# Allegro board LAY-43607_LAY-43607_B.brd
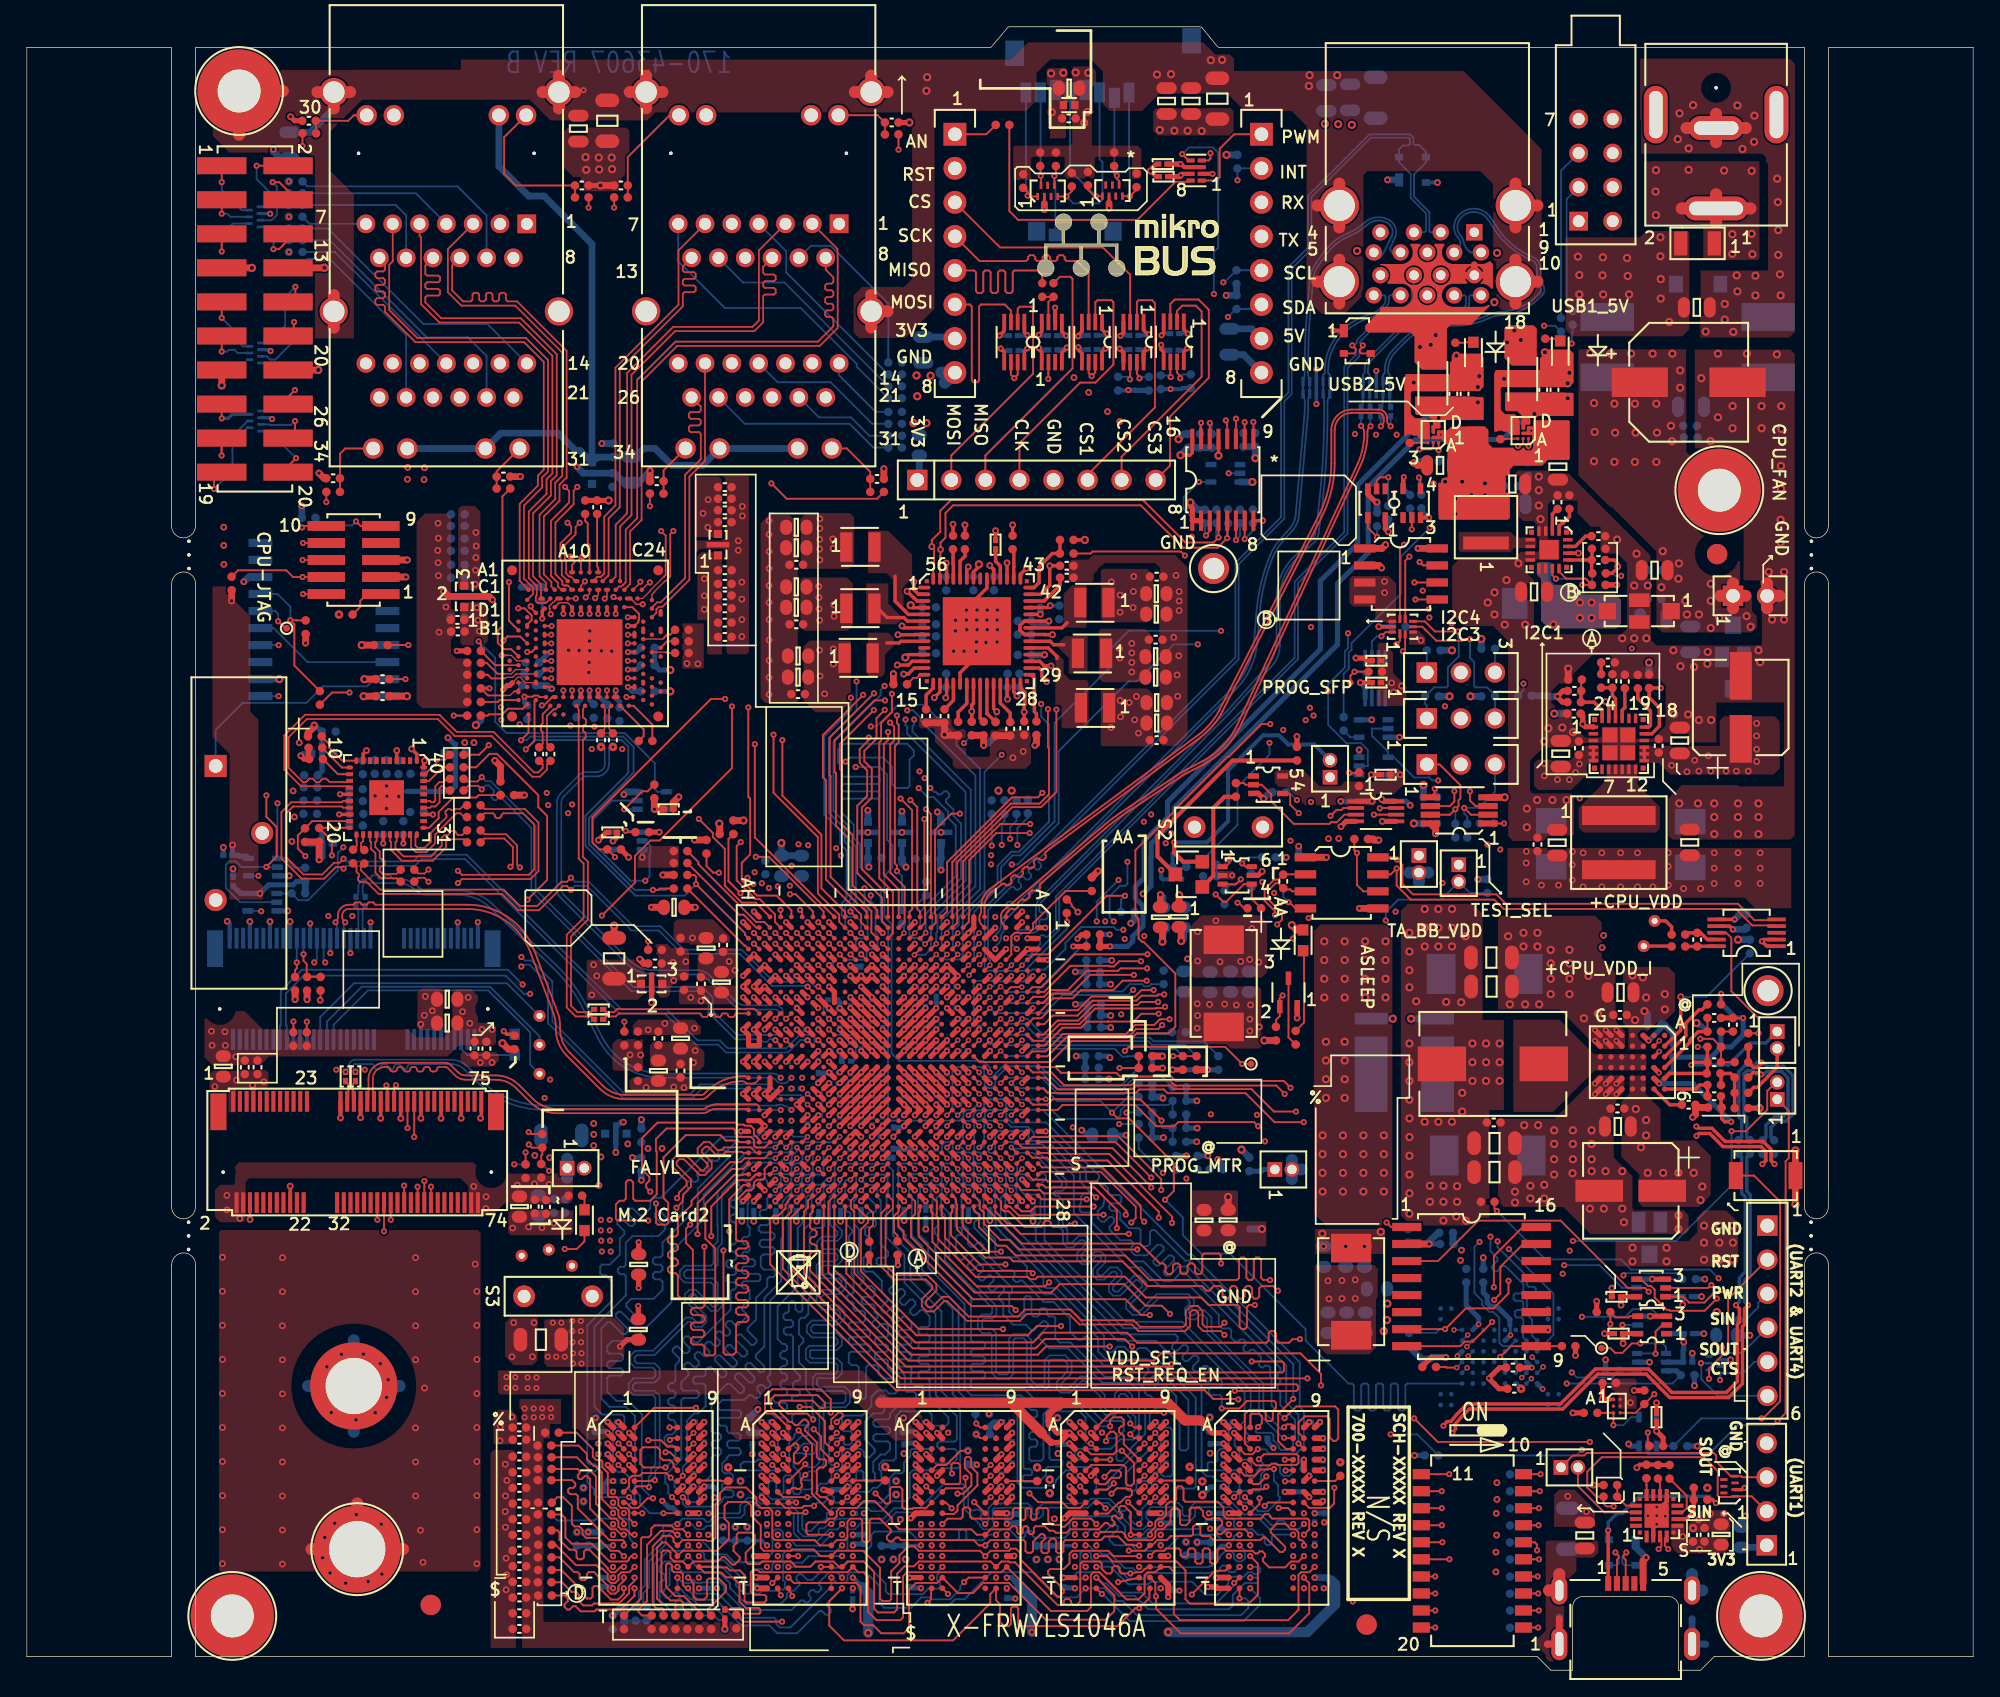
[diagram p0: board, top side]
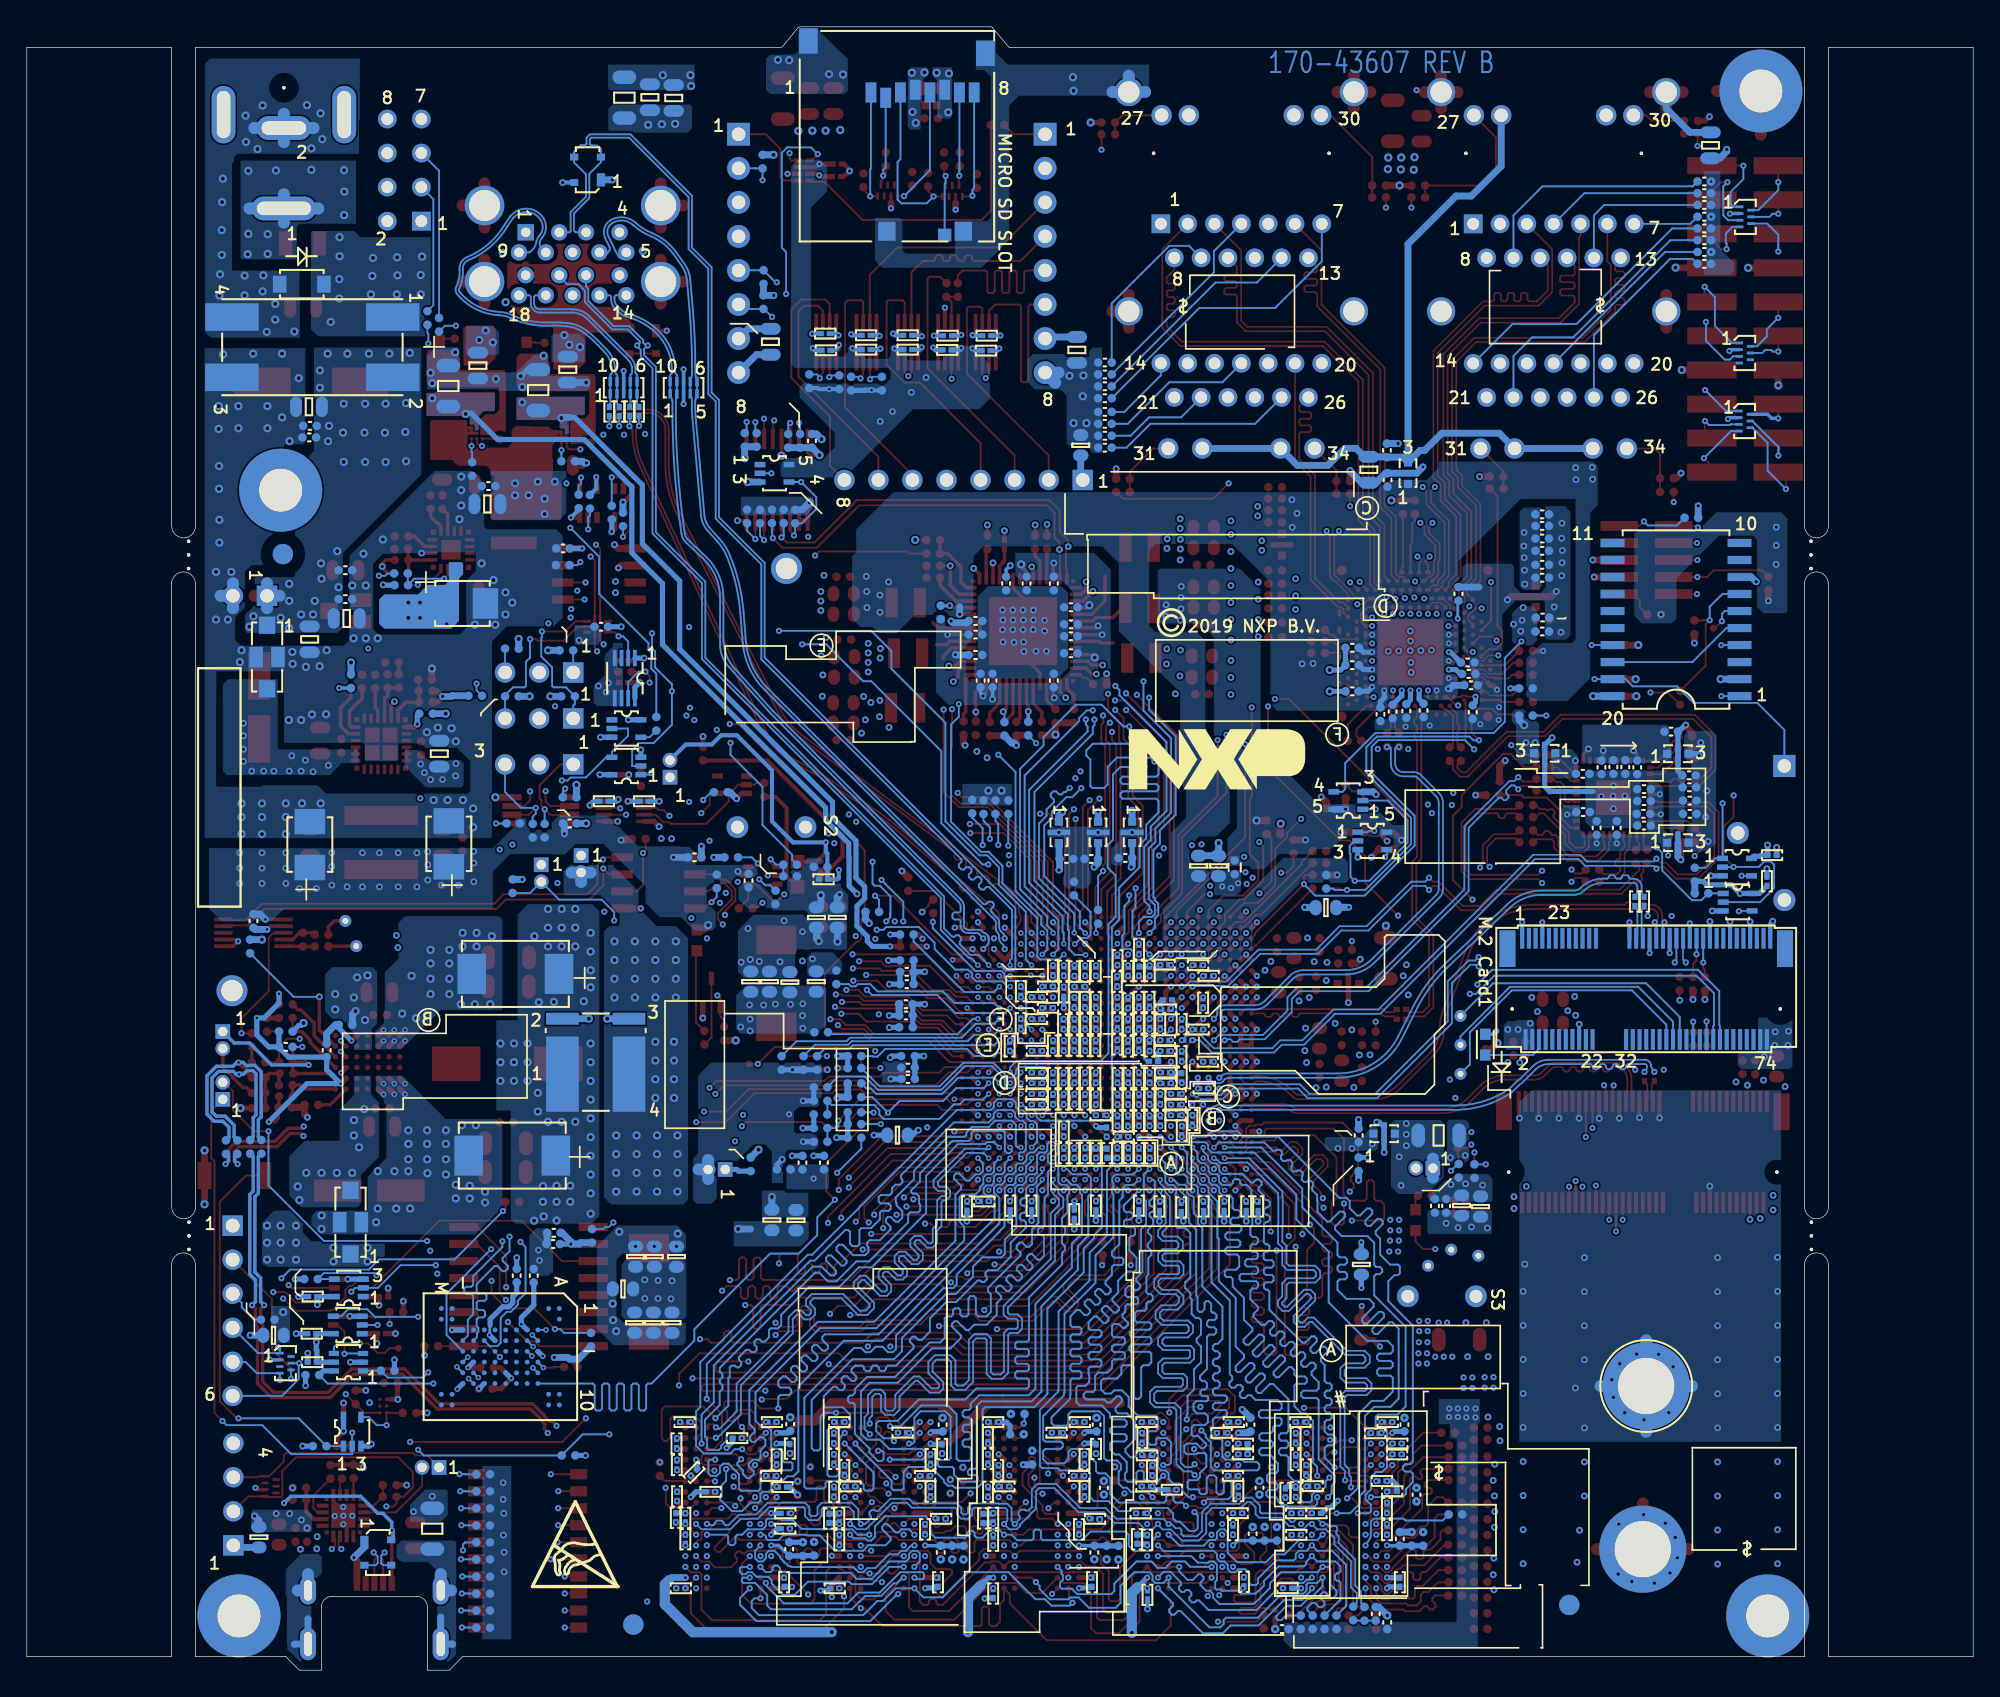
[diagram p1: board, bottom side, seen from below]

Outline 145.16 x 122.6 mm; copper layers: TOP, L2_GND, L3_INT_1, L4_INT_2, L5_PWR, BOTTOM. Coordinates in mm from the lower left corner of the outline.
Outline path: 0,121.05 10.8,121.05 10.8,85.36 arc(11.68,84.47) 12.57,85.36 12.57,121.05 71.8,121.05 arc(71.88,121.06) 71.94,121.1 73.14,122.54 arc(73.2,122.58) 73.26,122.6 87.45,122.6 arc(87.56,122.58) 87.66,122.51 88.77,121.15 arc(88.87,121.08) 88.99,121.05 132.57,121.05 132.57,85.36 arc(133.46,84.47) 134.35,85.36 134.36,85.36 134.36,121.05 145.16,121.05 145.16,1.02 134.36,1.02 134.36,30.24 arc(133.47,31.13) 132.58,30.24 132.57,1.02 125.84,1.02 124.83,0 123.19,0 123.19,4.7 arc(122.96,5.27) 122.39,5.5 116.09,5.5 arc(115.52,5.27) 115.29,4.7 115.29,0 113.65,0 112.64,1.01 112.63,1.02 12.57,1.02 12.58,30.24 arc(11.69,31.13) 10.81,30.24 10.8,30.24 10.8,1.02 0,1.02 0,121.05 ; 10.81,81.04 10.8,34.56 arc(11.68,33.67) 12.57,34.56 12.58,81.04 arc(11.69,81.93) 10.81,81.04 ; 132.58,81.04 132.57,34.56 arc(133.46,33.67) 134.35,34.56 134.36,81.04 arc(133.47,81.93) 132.58,81.04

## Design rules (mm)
constraint set DEFAULT: min track width 0.137
net group D1_MDQS8: nets D1_MDQS8_N D1_MDQS8_P
net group DP1: nets N26564871 N26564875
net group ETH_QSG3_MDI1: nets QSG3_MDI1_N QSG3_MDI1_P
net group QSGMII_RX_C: nets N29074387 N29074390
net group PH: nets IFC_CLE IFC_WE_B IFC_WP_B
net group POWER: nets 2V5_LED
net group SD_CLK: nets SOC_SD_CLK
net group U50: nets I2C_ADDR_A0 M2_1_REFCLK_EN# M2_2_REFCLK_EN#

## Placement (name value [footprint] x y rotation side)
BH5  -  [PMC_MECH_HOLE]  15.83 117.81 0 top
BH6  -  [PMC_MECH_HOLE]  15.32 4.05 0 top
BH7  -  [PMC_MECH_HOLE]  129.33 4.05 0 top
BH8  -  [PMC_MECH_HOLE]  126.22 88.03 0 top
BH9  -  [MH_C256-165T]  24.64 9.03 0 top
BH10  -  [MH_C256-165T]  24.38 21.2 180 bottom
BT3  -  [SKT_BAT_225X886_3V]  14.08 67.45 270 top
C5  -  [8X10P8]  123.94 96.08 0 top
C12  -  [CC0402_25]  121.4 79.9 180 bottom
C14  -  [CC0805_OV]  121.4 82.06 180 top
C18  -  [CC0402_25]  117.21 84.6 180 top
C19  -  [CC0402_25]  117.21 82.82 0 top
C20  -  [CC0805_OV]  110.79 88.49 0 top
C21  -  [CC0805_OV]  110.81 87 0 bottom
C22  -  [CC0402_25]  110.72 88.33 0 bottom
C24  -  [CC0805_OV]  118.86 50.56 180 top
C25  -  [CC0402_25]  118.81 48.88 180 top
C26  -  [CC0402_25]  118.63 41.9 180 top
C27  -  [CCE6P8X6P8]  119.62 35.77 180 top
C28  -  [CC0805_OV]  118.66 40.56 180 top
C29  22uF  [CC0805_OV]  124.55 101.67 0 top
C30  -  [CC0402_25]  124.04 92.83 0 bottom
C31  -  [CC0805_OV]  124.11 94.25 0 bottom
C32  -  [CC0402_25]  124.09 91.97 0 bottom
C36  -  [CC0402_25]  122.79 46.25 270 bottom
C113  -  [CC0402_25]  109.4 40.86 0 top
C114  100UF  [CC1206_OV]  109.22 53.16 0 top
C115  100UF  [CC1206_OV]  109.24 51 0 top
C116  100UF  [CC1206_OV]  109.46 37.16 0 top
C118  100UF  [CC1206_OV]  109.46 39.32 0 top
C119  -  [CC7343-31]  108.72 51.94 0 bottom
C120  -  [CC7343-31]  108.95 38.39 0 bottom
C122  100pF  [CC0402_25]  125.84 45.36 180 top
C125  -  [CC0402_25]  123.94 42.18 0 top
C126  -  [CC0402_25]  125.84 42.82 0 top
C127  56PF  [CC0402_25]  125.84 48.66 0 top
C128  -  [CC0402_25]  127.24 48.15 90 top
C148  -  [CC0201]  67.82 52.18 90 bottom
C149  -  [CC0201]  68.64 52.2 90 bottom
C151  -  [CC0402_25]  67.63 60.52 180 bottom
C152  -  [CC0201]  66.66 50.98 180 bottom
C153  -  [CC0201]  67.04 52.13 90 bottom
C155  -  [CC0402_25]  65.77 60.52 0 bottom
C156  -  [CC0201]  68.98 51.01 0 bottom
C157  -  [CC0201]  67.82 50.58 270 bottom
C159  -  [CC0402_25]  63.23 60.6 0 bottom
C160  -  [CC0201]  60.31 52.63 180 bottom
C161  -  [CC0603_OV]  57.77 60 90 bottom
C162  -  [CC0201]  65.08 41.39 180 bottom
C163  -  [CC0201]  71.04 48.27 90 bottom
C164  -  [CC0201]  63.03 49.74 90 bottom
C165  -  [CC0201]  63.82 49.85 270 bottom
C166  -  [CC0603_OV]  89.59 33.58 270 top
C167  -  [CC0603_OV]  89.59 33.58 270 bottom
C168  -  [CC0603_OV]  87.79 33.57 270 top
C169  -  [CC0603_OV]  84.54 56.18 90 top
C170  -  [CC0603_OV]  87.79 33.57 270 bottom
C171  -  [CC0603_OV]  86.27 56.15 90 bottom
C172  -  [CC0603_OV]  85.94 56.2 90 top
C173  -  [CC0603_OV]  84.72 56.15 90 bottom
C174  -  [CC0603_OV]  89.77 51.36 270 bottom
C175  -  [CC0603_OV]  91.17 51.36 270 bottom
C176  -  [CC0603_OV]  88.25 51.33 270 bottom
C180  -  [CC7343-31]  89.26 51.24 270 top
C181  -  [CC0201]  62.22 49.85 270 bottom
C182  -  [CC0201]  61.42 49.85 90 bottom
C183  -  [CC0201]  63.82 48.25 270 bottom
C184  -  [CC0201]  63.03 48.14 90 bottom
C185  -  [CC0201]  62.22 48.25 270 bottom
C186  -  [CC0201]  61.42 48.25 90 bottom
C187  -  [CC0201]  60.62 48.25 270 bottom
C188  -  [CC0201]  63.84 46.68 270 bottom
C189  -  [CC0201]  60.61 40.98 270 bottom
C190  -  [CC0201]  61.42 40.98 90 bottom
C191  -  [CC0201]  62.21 40.98 270 bottom
C193  -  [CC0201]  63.03 46.54 90 bottom
C194  -  [CC0201]  62.22 46.65 270 bottom
C195  -  [CC0201]  61.42 46.54 90 bottom
C196  -  [CC0201]  65.44 49.84 90 bottom
C197  -  [CC0201]  66.25 49.81 270 bottom
C198  -  [CC0201]  67.04 49.81 90 bottom
C199  -  [CC0201]  65.44 48.21 90 bottom
C200  -  [CC0201]  66.22 48.21 270 bottom
C201  -  [CC0201]  67.04 48.19 90 bottom
C202  -  [CC0201]  67.88 48.19 270 bottom
C203  -  [CC0201]  63.05 40.97 90 bottom
C204  -  [CC0201]  63.81 40.98 270 bottom
C205  -  [CC0201]  65.44 42.55 90 bottom
C206  -  [CC0201]  65.46 46.56 90 bottom
C207  -  [CC0201]  66.22 46.56 270 bottom
C208  -  [CC0201]  67.04 46.59 90 bottom
C209  -  [CC0201]  67.82 46.59 270 bottom
C210  -  [CC0201]  68.64 46.59 90 bottom
C211  -  [CC0201]  61.4 44.18 90 bottom
C212  -  [CC0201]  62.21 44.2 270 bottom
C213  -  [CC0201]  63 44.18 90 bottom
C214  -  [CC0201]  67.04 42.6 90 bottom
C215  -  [CC0201]  66.25 42.58 270 bottom
C216  -  [CC0201]  67.85 42.58 270 bottom
C217  -  [CC0201]  68.63 42.58 90 bottom
C218  -  [CC0201]  67.82 40.18 270 bottom
C219  -  [CC0201]  63.81 44.18 270 bottom
C220  -  [CC0201]  65.46 44.18 90 bottom
C221  -  [CC0201]  66.25 44.2 270 bottom
C222  -  [CC0201]  67.04 44.18 90 bottom
C223  -  [CC0201]  67.85 44.18 270 bottom
C224  -  [CC0201]  68.64 44.18 90 bottom
C225  -  [CC0201]  60.61 42.58 270 bottom
C226  -  [CC0201]  61.42 42.58 90 bottom
C227  -  [CC0201]  62.21 42.55 270 bottom
C228  -  [CC0201]  63.02 42.55 90 bottom
C229  -  [CC0201]  63.81 42.55 270 bottom
C230  -  [CC0402_25]  79.59 48.84 0 bottom
C231  -  [CC0402_25]  79.59 49.68 0 bottom
C232  -  [CC0201]  59.04 48.19 270 bottom
C233  -  [CC0402_25]  50.28 51.2 90 top
C234  -  [CC0603_OV]  51.8 51.33 90 top
C235  -  [CC0402_25]  79.44 44.1 0 bottom
C236  -  [CC0402_25]  79.44 44.95 0 bottom
C237  -  [CC0201]  57.8 52.6 180 bottom
C238  -  [CC0402_25]  51.93 54.09 270 top
C239  -  [CC0603_OV]  50.66 53.87 270 top
C240  -  [CC0402_25]  79.53 51.18 0 bottom
C241  -  [CC0201]  59.04 45.8 90 bottom
C242  -  [CC0402_25]  47.1 47.13 270 top
C243  -  [CC0402_25]  79.53 52.1 0 bottom
C244  -  [CC0603_OV]  48.75 47.13 270 top
C245  -  [CC0402_25]  85.71 37.86 90 bottom
C246  -  [CC0402_25]  87.31 37.86 90 bottom
C247  -  [CC0201]  59.02 44.2 90 bottom
C248  -  [CC0402_25]  48.75 44.72 90 top
C249  -  [CC0603_OV]  47.1 44.72 90 top
C252  100UF  [CC1206_OV]  39.86 39.9 180 bottom
C254  -  [CC0402_25]  45.83 39.9 90 bottom
C258  -  [CC0201]  59.48 41.4 180 bottom
C259  -  [CC0201]  59.48 42.2 180 bottom
C260  -  [CC0201]  59.48 43 180 bottom
C261  -  [CC0201]  60.2 43.77 180 bottom
C262  -  [CC0201]  60.23 44.58 180 bottom
C263  -  [CC0201]  60.28 46.19 180 bottom
C264  -  [CC0201]  60.28 46.99 180 bottom
C265  -  [CC0201]  60.2 49.29 180 bottom
C266  -  [CC0201]  58.22 41.05 270 bottom
C267  -  [CC0201]  57.39 43.4 180 bottom
C268  -  [CC0201]  57.08 45.4 180 bottom
C269  -  [CC0201]  57.77 47.8 0 bottom
C270  -  [CC0201]  57.43 49.79 270 bottom
C271  -  [CC0201]  57.02 51.81 180 bottom
C275  -  [CC0402_25]  46.85 52.72 180 top
C277  100UF  [CC1206_OV]  43.8 53.1 90 top
C278  0.1UF  [CC0402_25]  102.32 77.84 0 bottom
C279  -  [CC0603_OV]  99.76 30.85 90 bottom
C280  -  [CC0603_OV]  97.04 25.93 270 bottom
C281  -  [CC0603_OV]  99.83 25.93 270 bottom
C282  -  [CC0603_OV]  45.6 25.42 90 top
C283  -  [CC0603_OV]  45.63 30.27 90 bottom
C284  -  [CC0603_OV]  45.63 30.27 90 top
C285  -  [CC0603_OV]  98.44 25.93 270 bottom
C286  -  [CC0603_OV]  100.7 28.44 0 bottom
C287  -  [CC0603_OV]  98.36 30.85 90 bottom
C288  -  [CC7343-31]  98.77 28.24 90 top
C289  -  [CC0603_OV]  96.71 30.85 90 bottom
C290  -  [CC0201]  71.02 50.65 270 bottom
C291  -  [CC0201]  69.83 46.21 0 bottom
C292  -  [CC0201]  69.86 44.56 0 bottom
C293  -  [CC0201]  69.83 43.77 0 bottom
C294  -  [CC0201]  69.86 42.98 0 bottom
C295  -  [CC0201]  69.86 42.19 0 bottom
C296  -  [CC0603_OV]  86.28 51.37 270 bottom
C297  -  [CC0603_OV]  80.23 39.92 180 bottom
C298  -  [CC0201]  65.44 52.15 90 bottom
C299  -  [CC0201]  66.24 52.15 90 bottom
C300  -  [CC0603_OV]  48.27 56.89 180 bottom
C301  -  [CC0201]  63.81 52.95 90 bottom
C302  -  [CC0603_OV]  48.27 56.91 180 top
C303  -  [CC0201]  64.6 38.56 270 bottom
C304  -  [CC0201]  65.42 34.65 270 bottom
C305  -  [CC0201]  53.33 34.6 270 bottom
C306  -  [CC0201]  67.04 34.01 270 bottom
C307  -  [CC0201]  71.82 34.65 270 bottom
C308  -  [CC0201]  70.22 34.65 270 bottom
C309  -  [CC0201]  73.75 34.97 0 bottom
C310  -  [CC0201]  75.04 34.6 270 bottom
C311  -  [CC0201]  57.39 34.6 270 bottom
C312  -  [CC0201]  67.82 38.56 270 bottom
C313  -  [CC0201]  67.04 38.56 270 bottom
C314  -  [CC0201]  66.25 38.59 270 bottom
C315  -  [CC0201]  65.44 38.56 270 bottom
C316  -  [CC0201]  63.84 38.56 270 bottom
C317  -  [CC0201]  63 38.59 270 bottom
C318  -  [CC0201]  62.21 38.56 270 bottom
C319  -  [CC0201]  61.4 38.56 270 bottom
C320  -  [CC0201]  59.07 34.52 270 bottom
C321  -  [CC0201]  60.69 34.6 270 bottom
C322  -  [CC0201]  55.87 34.6 270 bottom
C323  -  [CC0201]  62.23 34.65 270 bottom
C324  -  [CC0201]  54.21 34.6 270 bottom
C328  -  [CC0201]  71.86 46.54 270 bottom
C329  -  [CC0201]  85.74 59 0 bottom
C330  -  [CC0603_OV]  56.29 60 90 bottom
C332  -  [CC0201]  61.41 52.15 90 bottom
C333  -  [CC0201]  62.21 52.15 90 bottom
C334  -  [CC0201]  63.01 52.15 90 bottom
C336  -  [CC0201]  63.86 51.36 270 bottom
C337  -  [CC0201]  59.02 40.25 270 bottom
C338  -  [CC0201]  62.21 53.78 90 bottom
C364  -  [CC0201]  61.25 14.89 90 bottom
C365  -  [CC0201]  56.06 17.71 180 bottom
C366  -  [CC0201]  55.2 14.49 180 bottom
C367  -  [CC0201]  61.58 5.62 270 bottom
C369  -  [CC0402_25]  53.9 18.32 90 bottom
C374  -  [CC0201]  61.66 13.71 180 bottom
C375  -  [CC0201]  61.62 16.02 180 bottom
C383  -  [CC0201]  54.39 6.59 270 bottom
C384  -  [CC0201]  55.14 18.51 0 bottom
C386  -  [CC0805_OV]  41.13 115 270 top
C388  -  [CC0805_OV]  19.59 113.76 270 bottom
C402  10uF  [CC0402_25]  51.55 3.07 0 bottom
C403  10uF  [CC0402_25]  36.74 3.08 180 top
C408  -  [CC0402_25]  36.74 10.09 180 top
C409  -  [CC0402_25]  36.74 4.25 180 top
C410  -  [CC0402_25]  36.74 15.93 180 top
C431  -  [CC0402_25]  44.56 4.2 270 bottom
C437  -  [CC0402_25]  93.7 58.84 90 top
C438  -  [CC0402_25]  91.33 58.91 270 bottom
C449  0.1uF  [CC0201]  73.62 98.44 180 bottom
C450  0.1uF  [CC0201]  73.57 99.56 180 bottom
C451  -  [CC0201]  82.56 98.52 180 bottom
C452  -  [CC0201]  82.56 99.59 180 bottom
C453  -  [CC0201]  76.52 98.49 0 bottom
C454  -  [CC0201]  76.49 99.56 0 bottom
C457  -  [CC0805_OV]  114.18 89.78 270 top
C458  1uF  [CC0402_25]  113.93 95.52 90 top
C459  -  [CC1206_OV]  113.73 95.8 90 bottom
C460  4.7UF  [CC0402_25]  113.09 95.52 90 top
C463  -  [CC0201]  101.71 93.9 270 bottom
C464  -  [CC0201]  100.98 93.9 270 bottom
C487  -  [CC0201]  123.87 22.98 0 bottom
C488  -  [CC0402_25]  118.02 21.43 0 top
C489  -  [CC0201]  121.54 18.88 90 top
C492  -  [CC0201]  118.7 25.11 180 top
C493  0.1uF  [CC0201]  15.38 58.85 90 bottom
C497  -  [CC0201]  15 60.8 180 bottom
C498  -  [CC0201]  47.87 64.23 0 top
C517  -  [CC0201]  49.26 13.73 0 bottom
C518  -  [CC0201]  61.96 17.33 270 bottom
C519  -  [CC0201]  54.46 16.91 180 bottom
C520  -  [CC0201]  61.6 9.71 270 bottom
C521  -  [CC0201]  51.29 13.23 270 bottom
C522  -  [CC0201]  54.8 13.36 270 bottom
C523  -  [CC0201]  54.46 16.11 180 bottom
C524  -  [CC0201]  61.66 18.51 180 bottom
C668  -  [CC0402_25]  53.23 13.61 270 bottom
C669  -  [CC0402_25]  53.73 10.18 90 bottom
C693  1uF  [CC0402_25]  42.53 86.76 90 top
C729  0.01UF  [CC0402_25]  43.72 91 90 bottom
C772  0.1UF  [CC0402_25]  64.76 94.89 0 bottom
C787  1uF  [CC0402_25]  32.12 78.35 180 top
C788  1uF  [CC0402_25]  32.14 81.5 180 bottom
C789  1uF  [CC0402_25]  52.06 87.39 0 top
C798  1uF  [CC0402_25]  52.06 80.18 0 top
C847  -  [CC0402_25]  43.71 69.38 90 top
C848  -  [CC0402_25]  42.82 69.38 90 top
C849  -  [CC0402_25]  38.21 68.34 90 top
C850  -  [CC0402_25]  39.05 68.34 90 top
C851  0.1UF  [CC0402_25]  32.14 77.49 180 bottom
C852  -  [CC0402_25]  37.32 71.47 270 bottom
C853  -  [CC0402_25]  42.28 71.56 270 bottom
C854  -  [CC0402_25]  37.62 74.32 180 bottom
C855  -  [CC0402_25]  37.7 75.18 180 bottom
C905  -  [CC0201]  123.91 25.1 0 bottom
C933  -  [CC0201]  69.83 48.57 180 bottom
C934  -  [CC0201]  69 49.42 180 bottom
C935  -  [CC0201]  69.83 50.22 180 bottom
C936  -  [CC0201]  63.35 39.81 180 bottom
C1000  0.1UF  [CC0402_25]  32.14 85.36 180 bottom
C1001  0.1UF  [CC0402_25]  32.14 86.22 180 bottom
C1003  -  [CC0402_25]  38.39 80.29 90 bottom
C1004  -  [CC0402_25]  40.99 71.6 270 bottom
C1005  -  [CC0402_25]  43.29 71.52 270 bottom
C1007  0.1UF  [CC0402_25]  32.14 84.42 180 bottom
C1008  0.1UF  [CC0402_25]  32.14 83.51 180 bottom
C1009  -  [CC0402_25]  52.06 81.04 0 top
C1010  -  [CC0402_25]  52.06 82.06 0 top
C1011  -  [CC0402_25]  52.06 78.15 0 top
C1013  -  [CC0402_25]  52.06 77.08 0 top
C1015  -  [CC0402_25]  44.21 71.32 270 bottom
C1016  -  [CC0402_25]  46.31 74.97 0 bottom
C1017  -  [CC0402_25]  46.31 76.27 0 bottom
C1018  -  [CC0402_25]  46.31 73.02 0 bottom
C1019  -  [CC0402_25]  37.45 73.47 180 bottom
C1020  1uF  [CC0402_25]  52.06 85.64 0 top
C1021  0.1UF  [CC0402_25]  64.76 95.78 0 bottom
C1022  0.1UF  [CC0402_25]  64.76 96.66 0 bottom
C1023  0.1UF  [CC0402_25]  64.76 97.55 0 bottom
C1024  0.1UF  [CC0402_25]  64.76 93.87 180 bottom
C1103  -  [CC0402_25]  43.67 88.79 90 bottom
C1104  4.7uF  [CC0805_OV]  45.07 89.55 270 bottom
C1139  100pF  [CC0402_25]  46.98 88.7 180 top
C1140  100pF  [CC0402_25]  63.41 88.87 0 top
C1141  100pF  [CC0402_25]  44.31 110.76 180 top
C1142  100pF  [CC0402_25]  64.5 115.46 0 top
C1143  0.1UF  [CC0402_25]  64.76 92.09 180 bottom
C1144  0.1UF  [CC0402_25]  64.76 92.98 180 bottom
C1145  0.1UF  [CC0402_25]  64.76 91.2 180 bottom
C1146  0.1UF  [CC0402_25]  20.05 107.55 0 bottom
C1147  0.1UF  [CC0402_25]  20.05 106.68 0 bottom
C1148  0.1UF  [CC0402_25]  20.05 105.8 0 bottom
C1149  0.1UF  [CC0402_25]  20.05 104.92 0 bottom
C1150  -  [CC0402_25]  41.39 110.76 0 top
C1151  -  [CC0402_25]  21.04 115.59 180 top
C1152  0.1UF  [CC0402_25]  20.05 108.43 180 bottom
C1153  0.1UF  [CC0402_25]  20.05 109.31 180 bottom
C1154  0.1UF  [CC0402_25]  20.05 110.18 180 bottom
C1155  0.1UF  [CC0402_25]  20.05 111.06 180 bottom
C1156  -  [CC0402_25]  22.85 88.92 180 top
C1157  -  [CC0402_25]  35.55 89.04 0 top
C1166  0.22uF  [CC0201]  25.23 57.35 90 bottom
C1168  0.22uF  [CC0201]  24.54 57.35 90 bottom
C1174  10uF  [CC0603_OV]  31.35 48.28 180 top
C1248  -  [CC0402_25]  110.83 22.57 180 top
C1249  -  [CC0402_25]  107.35 29.43 90 bottom
C1251  -  [CC0402_25]  108.62 29.43 90 bottom
C1253  -  [CC0402_25]  26.53 73.93 180 top
C1255  -  [CC0402_25]  26.53 72.66 180 top
C1256  -  [CC0402_25]  95.36 60.64 180 bottom
C1258  -  [CC0402_25]  105.17 83.68 0 bottom
C1259  -  [CC0402_25]  86.6 91.71 90 bottom
C1271  -  [CC0402_25]  21.16 65.86 0 bottom
C1272  -  [CC0402_25]  21.19 66.75 0 bottom
C1273  -  [CC0402_25]  22.53 70.02 180 bottom
C1274  1uF  [CC0402_25]  25.94 67.38 270 bottom
C1275  1uF  [CC0402_25]  25.05 67.35 270 bottom
C1276  1uF  [CC0402_25]  27.72 67.35 270 bottom
C1277  -  [CC0402_25]  26.83 67.38 270 bottom
C1278  1uF  [CC0402_25]  29.12 66.87 180 bottom
C1280  -  [CC0805_OV]  111.52 97.32 270 bottom
C1282  10uF  [CC0603_OV]  14.65 45.04 270 top
C1283  10uF  [CC0603_OV]  31.35 50.06 180 top
C1293  0.22uF  [CC0201]  23.77 44.29 90 top
C1294  0.22uF  [CC0201]  24.51 44.29 90 top
C1295  -  [CC0402_25]  105.9 31.79 0 bottom
C1296  -  [CC0402_25]  105.85 32.63 0 bottom
C1297  -  [CC0201]  123.84 27.87 0 bottom
C1298  -  [CC0603_OV]  77.73 118.03 180 top
C1299  -  [CC0402_25]  77.71 115.77 180 top
C1302  -  [CC0402_25]  125.12 10.1 90 top
C1304  -  [CC0603_OV]  126.35 10.12 90 top
C1305  -  [CC0402_25]  104.67 63.17 180 bottom
C1306  -  [CC0201]  79.46 98.52 180 bottom
C1307  -  [CC0201]  79.46 99.59 180 bottom
C1308  -  [CC0201]  85.56 98.47 180 bottom
C1309  -  [CC0201]  85.61 99.71 180 bottom
C1310  -  [CC0603_OV]  66.56 91.38 90 bottom
C1313  -  [CC0805_OV]  66.85 98.49 270 bottom
C1314  -  [CC0201]  43.67 62.5 0 top
C1315  -  [CC0201]  101.33 66.81 180 top
C1316  -  [CC0201]  84.77 111.42 180 top
C1317  -  [CC0201]  84.72 112.36 180 top
C1318  -  [CC0201]  102.12 64.82 0 bottom
C1319  -  [CC0201]  99.12 64.82 180 bottom
C1320  47uF  [CC0805_OV]  105.4 89.88 180 top
C1321  1uF  [CC0402_25]  107.22 95.22 90 top
C1322  4.7UF  [CC0402_25]  106.39 95.22 90 top
C1323  100UF  [CC1206_OV]  107.02 95.5 90 bottom
C1324  47uF  [CC0805_OV]  104.81 97.02 270 bottom
C1325  -  [CC0201]  100.19 93.9 90 bottom
C1326  -  [CC0201]  99.5 93.9 90 bottom
C1327  -  [CC0201]  100.65 75.3 0 top
C1328  -  [CC0201]  100.65 73.68 0 top
C1329  -  [CC0805_OV]  89.7 99.1 270 bottom
C1330  -  [CC0402_25]  121.4 82.06 180 bottom
C1331  22uF  [CC3528-21]  112.67 79.58 180 bottom
C1332  4.7uF  [CC0805_OV]  112.41 80.45 180 top
C1333  -  [CC0402_25]  114.16 87.14 270 top
C1334  -  [CC0402_25]  128.26 55.9 270 bottom
C1335  -  [CC0402_25]  124.57 54.5 90 top
C1337  -  [CC3528-21]  113.68 61.65 90 bottom
C1338  -  [CC3528-21]  124.05 61.59 90 bottom
C1339  -  [CC0805_OV]  114.13 61.73 90 top
C1340  -  [CC0805_OV]  124.02 61.75 90 top
C1341  -  [CC0402_25]  115.41 73.06 0 top
C1342  1uF  [CC0402_25]  115.38 71.36 0 top
C1343  -  [CC0402_25]  117.92 75.18 0 top
C1344  -  [CC0402_25]  119.18 73.76 90 top
C1345  -  [CC0805_OV]  124.06 76.9 270 bottom
C1346  -  [CCE6P8X6P8]  127.82 71.82 90 top
C1347  -  [CC0805_OV]  123.27 69.35 90 top
C1348  -  [CC0402_25]  121.7 68.96 90 top
C1349  -  [CC0201]  55.2 10.45 90 bottom
C1350  -  [CC0201]  54.86 11.71 180 bottom
C1351  -  [CC0201]  59.76 13.47 0 bottom
C1352  -  [CC0402_25]  36.74 12.43 180 top
C1353  -  [CC0402_25]  36.74 14.77 180 top
C1354  -  [CC0402_25]  36.74 13.6 180 top
C1355  -  [CC0402_25]  36.74 8.92 180 top
C1356  -  [CC0402_25]  36.74 7.76 180 top
C1357  -  [CC0402_25]  36.74 6.59 180 top
C1358  -  [CC0402_25]  43.7 3.57 90 bottom
C1359  -  [CC0402_25]  36.74 5.42 180 top
C1360  -  [CC0402_25]  36.74 11.26 180 top
C1361  10uF  [CC0402_25]  41.51 13.1 270 bottom
C1362  0.1uF  [CC0201]  43.33 13.35 180 bottom
C1363  0.1uF  [CC0201]  43.66 18.51 0 bottom
C1364  0.1uF  [CC0201]  50.49 11.7 0 bottom
C1365  0.1uF  [CC0201]  42.76 6.56 270 bottom
C1366  0.1uF  [CC0201]  44.6 17.67 180 bottom
C1367  0.1uF  [CC0201]  50.18 18.51 180 bottom
C1368  0.1uF  [CC0201]  50.53 13.26 270 bottom
C1369  0.1uF  [CC0201]  44.09 14.11 180 bottom
C1370  0.1uF  [CC0201]  42.96 16.1 180 bottom
C1371  0.1uF  [CC0201]  43.72 12.09 90 bottom
C1372  0.1uF  [CC0201]  43.72 10.45 90 bottom
C1373  0.1uF  [CC0201]  96.04 9.77 270 bottom
C1374  0.1uF  [CC0201]  42.95 16.91 180 bottom
C1375  0.1uF  [CC0201]  50.53 17.33 270 bottom
C1376  0.1uF  [CC0201]  48.98 11.7 180 bottom
C1377  0.1uF  [CC0201]  50.48 10.1 0 bottom
C1378  0.1uF  [CC0201]  50.53 15.68 270 bottom
C1379  0.1uF  [CC0201]  51.13 6.11 0 bottom
C1380  0.1uF  [CC0201]  49.77 14.97 90 bottom
C1382  10uF  [CC0402_25]  42.76 9.8 90 bottom
C1384  10uF  [CC0402_25]  42.42 18.32 90 bottom
C1385  -  [CC0402_25]  87.67 13.58 270 top
C1386  -  [CC0201]  96.38 6.11 0 bottom
C1387  -  [CC0201]  88.59 10.56 180 bottom
C1388  -  [CC0201]  95.4 14.75 135 bottom
C1389  -  [CC0201]  96.68 15.31 270 bottom
C1390  -  [CC0201]  96.66 12.97 270 bottom
C1391  -  [CC0201]  88.8 13.66 180 bottom
C1392  -  [CC0201]  88.59 11.7 180 bottom
C1393  -  [CC0201]  96.76 11.37 270 bottom
C1394  -  [CC0201]  92.18 17.31 0 bottom
C1395  -  [CC0201]  94.16 13.31 0 bottom
C1396  -  [CC0201]  62.36 9.77 270 bottom
C1397  -  [CC0201]  89.64 14.49 180 bottom
C1398  -  [CC0201]  96.1 18.51 180 bottom
C1399  -  [CC0201]  96.71 16.91 270 bottom
C1400  -  [CC0201]  62.09 11.7 0 bottom
C1401  -  [CC0201]  89.58 18.51 0 bottom
C1402  -  [CC0201]  88.68 6.56 270 bottom
C1403  -  [CC0201]  88.25 16.53 270 bottom
C1404  -  [CC0201]  89.24 15.71 270 bottom
C1406  -  [CC0402_25]  88.3 9.03 90 bottom
C1408  -  [CC0402_25]  88.22 18.36 90 bottom
C1409  10uF  [CC0402_25]  64.83 13.61 270 bottom
C1410  0.1uF  [CC0201]  76.9 16.5 270 bottom
C1411  0.1uF  [CC0201]  84.95 13.3 270 bottom
C1412  0.1uF  [CC0201]  77.76 13.33 270 bottom
C1413  0.1uF  [CC0201]  76.97 11.29 180 bottom
C1414  0.1uF  [CC0201]  84.19 14.93 90 bottom
C1415  0.1uF  [CC0201]  84.57 18.51 180 bottom
C1416  0.1uF  [CC0201]  84.56 9.71 270 bottom
C1417  0.1uF  [CC0201]  85.33 11.32 270 bottom
C1418  0.1uF  [CC0201]  96.04 11.37 270 bottom
C1419  0.1uF  [CC0201]  77.76 15.74 270 bottom
C1420  0.1uF  [CC0201]  84.56 11.37 270 bottom
C1421  0.1uF  [CC0201]  77.2 6.56 270 bottom
C1422  0.1uF  [CC0201]  84.97 17.29 270 bottom
C1423  0.1uF  [CC0201]  78.16 14.49 180 bottom
C1424  0.1uF  [CC0201]  83.73 13.71 0 bottom
C1425  0.1uF  [CC0201]  84.9 6.11 0 bottom
C1426  0.1uF  [CC0201]  84.96 15.77 270 bottom
C1427  0.1uF  [CC0201]  79.84 17.72 0 bottom
C1428  0.1uF  [CC0201]  78.17 10.51 90 bottom
C1430  10uF  [CC0402_25]  77 8.78 270 bottom
C1432  10uF  [CC0402_25]  76.86 18.32 90 bottom
C1433  -  [CC0402_25]  110.93 21 180 top
C1434  -  [CC0402_25]  21.14 64.87 0 bottom
C1435  -  [CC0402_25]  21.14 63.88 0 bottom
C1436  -  [CC0402_25]  24.59 63.88 0 bottom
C1437  1uF  [CC0402_25]  24.55 63.01 0 bottom
C1438  -  [CC0402_25]  24.55 65.73 0 bottom
C1439  -  [CC0402_25]  26.58 62.83 90 bottom
C1440  1uF  [CC0402_25]  29.09 64.02 180 bottom
C1441  -  [CC0402_25]  24.55 64.84 0 bottom
C1442  1uF  [CC0402_25]  28.08 62.83 90 bottom
C1443  0.1UF  [CC0402_25]  17.21 44.98 270 top
C1444  1uF  [CC0402_25]  16.26 44.98 270 top
C1445  0.1UF  [CC0402_25]  34.28 46.37 270 top
C1446  1uF  [CC0402_25]  33.39 46.37 270 top
C1447  10uF  [CC0603_OV]  38.16 34.66 270 bottom
C1448  10uF  [CC0603_OV]  36.74 34.59 270 bottom
C1449  10uF  [CC0603_OV]  36.74 34.59 270 top
C1450  0.1UF  [CC0402_25]  40.14 34.64 270 bottom
C1451  1uF  [CC0402_25]  39.3 34.64 270 bottom
C1452  0.1UF  [CC0402_25]  38.72 34.56 270 top
C1453  1uF  [CC0402_25]  37.88 34.59 270 top
C1454  10uF  [CC0402_25]  32.14 77.49 180 top
C1455  10uF  [CC0402_25]  32.12 78.53 180 bottom
C1456  10uF  [CC0402_25]  32.14 82.47 180 bottom
C1457  -  [CC0402_25]  52.06 88.26 0 top
C1458  -  [CC0402_25]  52.06 86.53 0 top
C1459  -  [CC0402_25]  52.06 79.21 0 top
C1460  -  [CC0805_OV]  98.69 117.34 270 bottom
C1461  -  [CC0805_OV]  96.91 117.29 270 bottom
C1462  -  [CC0805_OV]  85 117.06 270 top
C1463  -  [CC0805_OV]  86.83 117.06 270 top
C1464  -  [CC0402_25]  124.26 10.09 90 top
C1465  10uF  [CC0603_OV]  126.76 24.99 0 bottom
C1466  10uF  [CC0603_OV]  127.85 9.92 90 bottom
C1467  -  [CC0805_OV]  116.19 10.05 90 top
C1468  -  [CC0805_OV]  114.4 68.37 90 top
C1469  -  [CC0805_OV]  114.4 68.37 90 bottom
C1470  -  [CC0402_25]  112.66 61.6 90 top
C1471  22pF  [CC0402_25]  118.25 73.79 90 top
C1472  -  [CC0402_25]  125.84 46.5 0 bottom
C1475  22UF  [CC0603_OV]  57.39 85.26 180 top
C1476  22UF  [CC0603_OV]  57.39 83.74 180 top
C1481  -  [CC0402_25]  67.3 79.29 0 bottom
C1489  -  [CC0402_25]  67.3 78.02 0 bottom
C1490  -  [CC0402_25]  67.3 77.13 0 bottom
C1491  -  [CC0402_25]  67.3 75.86 0 bottom
C1492  -  [CC0402_25]  74.41 75.73 180 bottom
C1493  -  [CC0402_25]  74.41 77.26 180 bottom
C1494  -  [CC0402_25]  74.41 78.27 180 bottom
C1495  0.1UF  [CC0402_25]  57.39 82.47 180 top
C1520  22UF  [CC0603_OV]  57.39 79.29 180 top
C1521  22UF  [CC0603_OV]  57.39 80.81 180 top
C1523  0.1UF  [CC0402_25]  57.39 78.02 180 top
C1524  -  [CC0603_OV]  57.52 75.66 180 top
C1525  -  [CC0603_OV]  57.52 74.08 180 top
C1526  -  [CC0402_25]  57.52 72.81 180 top
C1530  -  [CC0603_OV]  84.26 72.18 0 top
C1531  -  [CC0603_OV]  84.26 70.65 0 top
C1532  -  [CC0402_25]  84.26 69.38 0 top
C1533  -  [CC0603_OV]  84.19 74.08 0 top
C1534  -  [CC0603_OV]  84.19 75.61 0 top
C1535  -  [CC0402_25]  84.19 76.88 0 top
C1536  -  [CC0603_OV]  84.24 80.31 0 top
C1537  -  [CC0603_OV]  84.24 78.78 0 top
C1538  -  [CC0402_25]  84.26 81.58 0 top
C1540  -  [CC0402_25]  77.56 82.39 0 top
C1542  -  [CC0402_25]  70.6 81.07 270 bottom
C1544  -  [CC0402_25]  68.57 81.07 270 bottom
C1545  -  [CC0402_25]  77.56 81.5 0 top
C1546  -  [CC0201]  72.25 83.97 90 top
C1547  -  [CC0402_25]  74.03 73.83 90 bottom
C1548  -  [CC0402_25]  73.14 73.83 90 bottom
C1549  -  [CC0402_25]  68.57 73.83 90 bottom
C1550  -  [CC0402_25]  72.12 81.07 270 bottom
C1551  -  [CC0402_25]  74.38 70.27 270 top
C1552  -  [CC0402_25]  67.07 71.18 270 top
C1553  -  [CC0402_25]  68.44 71.18 270 top
C1554  -  [CC0402_25]  73.34 70.22 270 top
C1555  -  [CC0201]  118.55 27.86 180 top
C1556  -  [CC0402_25]  76.29 13.71 270 top
C1557  -  [CC0201]  65.72 6.56 270 bottom
C1558  -  [CC0201]  66.69 10.51 90 bottom
C1559  -  [CC0201]  66.28 13.33 270 bottom
C1560  -  [CC0201]  73.09 9.66 270 bottom
C1561  -  [CC0201]  73.47 13.3 270 bottom
C1562  -  [CC0201]  73.09 18.51 180 bottom
C1563  -  [CC0201]  72.25 13.71 0 bottom
C1564  -  [CC0201]  73.48 17.36 270 bottom
C1565  -  [CC0201]  73.08 11.37 270 bottom
C1566  -  [CC0201]  73.09 5.72 270 bottom
C1567  -  [CC0201]  65.49 11.29 180 bottom
C1568  -  [CC0201]  68.36 17.72 0 bottom
C1569  -  [CC0201]  66.68 14.49 180 bottom
C1570  -  [CC0201]  73.85 11.32 270 bottom
C1571  -  [CC0201]  66.28 15.74 270 bottom
C1572  -  [CC0201]  65.42 16.5 270 bottom
C1573  -  [CC0201]  72.71 14.93 90 bottom
C1574  -  [CC0201]  66.62 18.51 0 bottom
C1575  -  [CC0201]  73.48 15.77 270 bottom
C1577  -  [CC0402_25]  65.54 8.78 270 bottom
C1579  -  [CC0402_25]  65.38 18.32 90 bottom
C1581  -  [CC0402_25]  115.75 68.78 90 top
C1582  -  [CC0201]  42.65 49.3 0 top
C1583  -  [CC0201]  42.65 48.56 0 top
C1584  10uF  [CC0402_25]  36.73 18.1 180 top
C1585  10uF  [CC0402_25]  36.74 17.19 180 top
C1586  100UF  [CC1206_OV]  38.34 24.66 180 top
C1587  -  [CC0805_OV]  121.3 78.46 180 bottom
D2  LED_YELLOW  [LED_0603]  95.18 54.45 270 top
D4  LED_GREEN  [LED_0603]  114.36 98.39 270 top
D6  -  [SOD123]  124.65 103.4 0 bottom
D508  LED_GREEN  [LED_0603]  107.88 98.29 270 top
D509  -  [LED_QUAD_2P54_TH]  115.73 108.1 270 top
D510  LED_GREEN  [LED_0603]  36.39 46.67 270 bottom
D511  LED_GREEN  [LED_0603]  41.59 33.57 270 top
F2  -  [FUSE_3P4X1P8]  124.6 106.44 180 top
FL2  -  [CC_NFM41P_1806]  120.25 79.01 180 top
FL3  NFM18PC225B1A3  [CC0603_NFM18PC]  68.18 62.5 270 bottom
FL4  NFM18PC225B1A3  [CC0603_NFM18PC]  65.26 62.5 270 bottom
FL5  NFM18PC225B1A3  [CC0603_NFM18PC]  62.72 62.5 270 bottom
FL7  NFM18PC225B1A3  [CC0603_NFM18PC]  43.93 40.02 180 bottom
FL8  NFM18PC225B1A3  [CC0603_NFM18PC]  46.59 51.2 0 top
FL18  -  [CC0603_NFM18PC]  51.55 83.96 90 top
FL19  NFM18PC225B1A3  [CC0603_NFM18PC]  32.62 80.1 90 top
FL22  -  [CC0603_NFM18PC]  42.15 89.3 90 bottom
FL28  NFM18PC225B1A3  [CC0603_NFM18PC]  22.02 68.37 180 bottom
FL29  NFM18PC225B1A3  [CC0603_NFM18PC]  31.96 68.4 0 bottom
FL30  NFM18PC225B1A3  [CC0603_NFM18PC]  22.02 61.73 180 bottom
FL31  -  [CC_NFM41P_1806]  127.24 75.58 270 bottom
FL32  -  [CC_NFM41P_1806]  121.02 33.42 90 bottom
J1  -  [CON_DCJACK_063BH_TH_RA]  125.98 109.05 0 top
J8  HDR_1X2  [HDR1X2_50MIL]  130.54 47.64 0 top
J9  HDR_1X2  [HDR1X2_50MIL]  103.82 60.77 0 top
J11  HDR_1X2  [HDR1X2_50MIL]  93.08 37.36 90 top
J12  HDR_1X2  [HDR1X2_50MIL]  40.3 37.45 90 top
J13  HDR_1X2  [HDR1X2_50MIL]  106.79 60.09 0 top
J14  HDR_1X2  [HDR1X2_50MIL]  130.54 42.59 180 top
J15  FTSH-105-01-L-DV-K  [HDR205_10M_50_SM_K]  24.37 82.82 90 top
J46  M.2 SKT  [CON_67_0P5_22X7P75_RA]  24.38 50.7 180 bottom
J52  M.2 SKT  [CON_67_0P5_22X7P75_RA]  24.64 38.53 0 top
J55  95220030-14RRF  [CON_SDCARD_95220]  80.26 114.44 180 bottom
J56  -  [CON_1X8_SKT_2P54_TH]  69.22 114.58 0 top
J57  -  [CON_1X8_SKT_2P54_TH]  92.08 114.58 0 top
J58  CON SKT MICRO-B  [CON_USB_5F_0P65_SM_RA_B]  119.24 1.8 0 top
J60  HDR 1X6  [HDR106_TH_TSW]  129.8 33.16 0 top
J63  HDR_1X3  [HDR103]  104.41 74.43 90 top
J64  HDR_1X3  [HDR103]  104.41 71 90 top
J65  HDR_1X3  [HDR103]  104.41 67.57 90 top
J66  -  [JUMP1X8-6040]  66.41 88.79 90 top
J67  -  [CON_TSM_20M_2P54_SM]  17.01 100.8 270 top
J70  -  [CON_18P_USB3_RA_TH]  107.95 107.27 270 top
J72  HDR_1X2  [HDR1X2_50MIL]  114.41 15.13 90 top
J73  HDR 1X4  [JUMP1X4-6040]  129.75 9.31 90 top
J74  HDR_1X2  [HDR1X2_50MIL]  97.19 66.62 180 top
J75  HDR 1X2  [HDR102]  127.24 80.15 90 top
L2  -  [IND4_7X13_SM]  123.86 98.7 270 bottom
L9  -  [IND2_744308033]  109.33 45.23 270 top
L11  -  [IND_NFE31P]  111.57 96.31 90 top
L56  -  [IND_0402]  55.08 59.89 270 bottom
L514  NFE31PT222Z1E9L  [IND_NFE31P]  104.86 96 90 top
L515  -  [IND2_4P3SQ_XFL4020]  108.83 85.27 90 top
L516  -  [IND2_XAL60XX_102]  118.73 61.74 270 top
L531  -  [IND2520]  62.16 83.79 0 top
L532  -  [IND2520]  62.16 79.21 0 top
L533  -  [IND2520]  62.04 75.51 0 top
L535  -  [IND2520]  79.66 71.8 180 top
L536  -  [IND2520]  79.44 75.86 180 top
L537  -  [IND2520]  79.61 79.65 180 top
NOREF  -  []  115.73 108.1 90 top
NOREF#2  -  []  113.66 93.31 90 top
NOREF#3  -  []  134.05 38.65 90 top
NOREF#4  -  []  98.22 98.23 90 top
NOREF#5  -  []  78.9 117.9 0 top
NOREF#6  -  []  73.08 6.11 90 top
NOREF#7  -  []  104.34 110.98 90 top
NOREF#8  -  []  87.63 111.13 90 top
NOREF#9  -  []  125.84 1.02 0 top
NOREF#10  -  []  47.64 58.6 0 top
NOREF#11  -  []  111.19 91.87 90 top
NOREF#12  -  []  100.45 102.57 0 top
NOREF#13  -  []  117.31 89 0 top
NOREF#14  -  []  124.11 89 90 top
NOREF#15  -  []  112.77 82.18 0 top
NOREF#16  -  []  78.43 109.75 90 top
NOREF#17  -  []  83.86 72.95 90 top
NOREF#18  -  []  37.32 73.35 0 top
NOREF#19  -  []  121.75 47.86 90 top
NOREF#20  -  [unnamed#2]  126.06 83.26 0 top
NOREF#21  -  []  47.27 73.02 0 top
NOREF#22  -  []  105.58 93.01 0 top
NOREF#23  -  [unnamed#2]  12.07 32.4 180 top
NOREF#24  -  []  13.64 34.51 90 top
NOREF#25  -  [unnamed#2]  12.07 33.42 180 top
NOREF#26  -  []  59.04 106.76 90 top
NOREF#27  -  []  41.74 33.23 90 top
NOREF#28  -  []  123.05 10.02 0 top
NOREF#29  -  []  136.13 31.95 90 top
NOREF#30  -  []  62.45 5.06 90 top
NOREF#31  -  []  34.38 49.33 90 top
NOREF#32  -  []  116.92 67.29 0 top
NOREF#33  -  []  115.29 0 0 top
NOREF#34  -  []  46.62 72.05 0 top
NOREF#35  -  []  121.02 31.04 90 top
NOREF#36  -  []  37.42 80.6 0 top
NOREF#37  -  [unnamed#2]  12.09 83.2 180 top
NOREF#38  -  []  14.08 67.45 0 top
NOREF#39  -  []  24.58 62.33 0 top
NOREF#40  -  []  120.2 33.42 0 top
NOREF#41  -  []  78.39 75.86 0 top
NOREF#42  -  []  78.56 79.65 0 top
NOREF#43  -  []  117.94 6.47 0 top
NOREF#44  -  []  99.17 19.19 270 top
NOREF#45  -  []  118.09 18.96 0 top
NOREF#46  -  []  114.09 0 90 top
NOREF#47  -  []  133.48 56.38 0 top
NOREF#48  -  []  107.95 107.27 0 top
NOREF#49  -  []  60.76 82.64 0 top
NOREF#50  -  []  81.01 107.34 90 top
NOREF#51  -  []  126.28 23.15 90 top
NOREF#52  -  []  15.83 117.81 0 top
NOREF#53  -  []  88.79 5.06 0 top
NOREF#54  -  []  14.29 41.66 90 top
NOREF#55  -  []  25.34 116 0 top
NOREF#56  -  []  16.57 107.92 0 top
NOREF#57  -  []  51.66 91.14 0 top
NOREF#58  -  []  81.01 80.8 0 top
NOREF#59  -  []  14.41 113.5 0 top
NOREF#60  -  []  85.05 83.05 90 top
NOREF#61  -  []  25.29 97.49 90 top
NOREF#62  -  []  131.71 38.65 0 top
NOREF#63  -  []  39.04 71.95 0 top
NOREF#64  -  []  104.99 58.62 90 top
NOREF#65  -  []  39.41 33.23 0 top
NOREF#66  -  []  28.37 91.14 0 top
NOREF#67  -  []  46.18 117.73 0 top
NOREF#68  -  []  63.44 74.36 90 top
NOREF#69  -  []  124.19 1.95 90 top
NOREF#70  -  []  113.52 10.91 0 top
NOREF#71  -  []  38.72 72.6 0 top
NOREF#72  -  []  106.96 93.01 90 top
NOREF#73  -  []  16.57 108.42 90 top
NOREF#74  -  []  39.37 72.6 0 top
NOREF#75  -  []  36.19 82.05 0 top
NOREF#76  -  []  66.8 73.46 0 top
NOREF#77  -  []  125.45 22.4 0 top
NOREF#78  -  []  23.83 62.09 90 top
NOREF#79  -  []  65.83 5.06 0 top
NOREF#80  -  []  56.87 29.06 0 top
NOREF#81  -  []  120 10.77 0 top
NOREF#82  -  []  60.64 74.36 0 top
NOREF#83  -  []  17.46 93.44 90 top
NOREF#84  -  []  25.34 116 0 top
NOREF#85  -  []  114.41 15.13 0 top
NOREF#86  -  []  49.58 105.36 0 top
NOREF#87  -  []  117.35 46.56 90 top
NOREF#88  -  []  120.63 69.86 90 top
NOREF#89  -  []  81.06 72.95 0 top
NOREF#90  -  []  91.47 85.76 90 top
NOREF#91  -  []  48.03 113.16 90 top
NOREF#92  -  []  50.12 17.31 90 top
NOREF#93  -  []  84.56 17.31 90 top
NOREF#94  -  []  132.39 74.74 0 top
NOREF#95  -  []  106.79 58.82 90 top
NOREF#96  -  []  38.62 79.2 0 top
NOREF#97  -  []  126.43 75.58 0 top
NOREF#98  -  []  121.23 67.11 90 top
NOREF#99  -  []  119.79 100.97 90 top
NOREF#100  -  []  96.04 17.31 90 top
NOREF#101  -  []  112.12 82.83 90 top
NOREF#102  -  []  36.19 71.15 0 top
NOREF#103  -  []  27.37 116 0 top
NOREF#104  -  []  100.22 98.23 90 top
NOREF#105  -  []  80.46 110.8 0 top
NOREF#106  -  []  131.71 45.48 90 top
NOREF#107  -  []  75.31 107.34 90 top
NOREF#108  -  []  54.35 5.06 0 top
NOREF#109  -  []  126.56 13.22 90 top
NOREF#110  -  []  61.6 6.11 90 top
NOREF#111  -  []  75.63 110.77 0 top
NOREF#112  -  []  37.32 72.05 0 top
NOREF#113  -  []  63.56 78.06 90 top
NOREF#114  -  []  36.66 72.37 0 top
NOREF#115  -  []  117.88 79.01 0 top
NOREF#116  -  []  85.41 5.06 90 top
NOREF#117  -  []  115.73 108.1 90 top
NOREF#118  -  []  63.1 124.04 0 top
NOREF#119  -  []  121.8 9.97 0 top
NOREF#120  -  []  42.29 75.3 0 top
NOREF#121  -  []  98.36 62.68 0 top
NOREF#122  -  []  82.2 117.7 0 top
NOREF#123  -  []  15.64 34.88 0 top
NOREF#124  -  []  113.18 121.05 0 top
NOREF#125  -  []  45.22 72.6 0 top
NOREF#126  -  []  127.58 14.82 0 top
NOREF#127  -  []  14.38 49.33 0 top
NOREF#128  -  []  97.05 120.71 0 top
NOREF#129  -  [unnamed#2]  99.92 3.4 0 top
NOREF#130  -  []  124.9 31.26 90 top
NOREF#131  -  []  126.05 10.02 90 top
NOREF#132  -  []  39.74 81.17 0 top
NOREF#133  -  []  119.98 7.83 90 top
NOREF#134  -  []  117.35 43.36 0 top
NOREF#135  -  []  60.99 75.51 0 top
NOREF#136  -  []  50.97 5.06 90 top
NOREF#137  -  []  128.78 14.82 90 top
NOREF#138  -  []  93.08 37.36 0 top
NOREF#139  -  []  59.04 106.76 90 top
NOREF#140  -  []  59.04 106.76 0 top
NOREF#141  -  []  112.28 93.31 0 top
NOREF#142  -  [unnamed#2]  133.07 31.39 0 top
NOREF#143  -  []  24.74 113.16 90 top
NOREF#144  -  []  15.32 4.05 0 top
NOREF#145  -  []  127.39 12.97 90 top
NOREF#146  -  []  36.66 72.37 0 top
NOREF#147  -  []  76.7 107.07 0 top
NOREF#148  -  []  81.01 107.34 90 top
NOREF#149  -  []  120.3 10.27 90 top
NOREF#150  -  []  92.19 33.14 0 top
NOREF#151  -  []  14.03 53.83 0 top
NOREF#152  -  []  41.97 75.95 0 top
NOREF#153  -  []  115.86 10.91 90 top
NOREF#154  -  []  25.83 91.14 0 top
NOREF#155  -  []  112.77 82.18 90 top
NOREF#156  -  []  48.03 113.16 90 top
NOREF#157  -  []  111.19 92.67 90 top
NOREF#158  -  []  15.64 34.88 0 top
NOREF#159  -  []  17.63 97.16 0 top
NOREF#160  -  []  -297.31 -257.43 0 top
NOREF#161  -  []  120.25 78.2 90 top
NOREF#162  -  []  126.22 88.03 0 top
NOREF#163  -  []  107.96 57.93 90 top
NOREF#164  -  []  28.38 47.05 0 top
NOREF#165  -  []  76.63 110.77 0 top
NOREF#166  -  []  102.8 77.27 90 top
NOREF#167  -  []  42.87 5.06 0 top
NOREF#168  -  []  24.58 62.33 0 top
NOREF#169  -  []  115.29 0 0 top
NOREF#170  -  []  126.56 14.22 0 top
NOREF#171  -  []  127.24 73.21 90 top
NOREF#172  -  []  117.23 67.11 0 top
NOREF#173  -  []  14.54 109.69 90 top
NOREF#174  -  []  24.07 62.84 90 top
NOREF#175  -  []  98.03 19.7 270 top
NOREF#176  -  []  40.34 81.25 0 top
NOREF#177  -  []  61.6 17.31 90 top
NOREF#178  -  []  115.73 108.1 0 top
NOREF#179  -  []  85.05 88.16 0 top
NOREF#180  -  []  80.15 124.04 90 top
NOREF#181  -  []  18.85 92.09 90 top
NOREF#182  -  []  122.65 79.96 0 top
NOREF#183  -  []  77.23 109.75 0 top
NOREF#184  -  []  14.64 37.16 90 top
NOREF#185  -  []  88.68 109.83 90 top
NOREF#186  -  []  35.38 46.68 90 top
NOREF#187  -  []  123.19 -0.48 90 top
NOREF#188  -  [unnamed#2]  30.12 4.87 0 top
NOREF#189  -  []  105.45 107.27 0 top
NOREF#190  -  []  56.86 124.03 90 top
NOREF#191  -  []  14.54 112.23 0 top
NOREF#192  -  []  48.58 107.9 0 top
NOREF#193  -  []  104.49 92.77 0 top
NOREF#194  -  [unnamed#2]  12.07 31.39 180 top
NOREF#195  -  []  97.19 66.62 90 top
NOREF#196  -  [unnamed#2]  133.09 83.2 0 top
NOREF#197  -  []  102.65 58.62 0 top
NOREF#198  -  []  17.59 107.32 0 top
NOREF#199  -  []  13.64 34.51 0 top
NOREF#200  -  []  41.97 75.95 0 top
NOREF#201  -  []  84.56 6.11 90 top
NOREF#202  -  []  121.02 31.04 90 top
NOREF#203  -  []  129.33 4.05 90 top
NOREF#204  -  []  49.12 91.14 0 top
NOREF#205  -  []  78.9 117.9 90 top
NOREF#206  -  []  94.52 33.14 90 top
NOREF#207  -  []  133.03 78.22 90 top
NOREF#208  -  []  47.09 71.15 0 top
NOREF#209  -  []  62.97 101.37 90 top
NOREF#210  -  []  17.83 62.09 0 top
NOREF#211  -  []  83.81 80.8 90 top
NOREF#212  -  []  117.48 67.21 0 top
NOREF#213  -  []  50.12 6.11 90 top
NOREF#214  -  []  63.56 82.64 90 top
NOREF#215  -  []  -270.64 263.65 0 top
NOREF#216  -  []  40.3 37.45 0 top
NOREF#217  -  []  115.38 123.25 90 top
NOREF#218  -  []  116.75 47.86 0 top
NOREF#219  -  []  105.62 57.93 0 top
NOREF#220  -  [unnamed#2]  133.09 84.22 0 top
NOREF#221  -  []  111.19 93.07 0 top
NOREF#222  -  []  59.04 122.11 0 top
NOREF#223  -  []  75.38 109.94 0 top
NOREF#224  -  []  43.92 72.6 0 top
NOREF#225  -  []  37.97 72.37 0 top
NOREF#226  -  []  74.9 73.46 90 top
NOREF#227  -  []  117.48 67.21 0 top
NOREF#228  -  []  36.19 71.15 0 top
NOREF#229  -  []  131.65 106.4 90 top
NOREF#230  -  []  37.42 71.3 0 top
NOREF#231  -  []  100.45 102.57 0 top
NOREF#232  -  []  73.19 106.76 90 top
NOREF#233  -  []  16.63 93.19 90 top
NOREF#234  -  []  125.45 22.9 90 top
NOREF#235  -  []  104.49 92.37 90 top
NOREF#236  -  []  90.09 82.19 0 top
NOREF#237  -  []  11.56 41.89 0 top
NOREF#238  -  []  130.54 46.37 90 top
NOREF#239  -  []  73.66 120.62 0 top
NOREF#240  -  [unnamed#3]  37.08 27.9 90 top
NOREF#241  -  []  112.21 82.27 0 top
NOREF#242  -  []  98.03 19.7 270 top
NOREF#243  -  []  76.7 107.07 90 top
NOREF#244  -  []  73.93 5.06 90 top
NOREF#245  -  []  61.11 79.21 0 top
NOREF#246  -  []  40.67 81.9 0 top
NOREF#247  -  []  37.42 71.3 0 top
NOREF#248  -  []  129.86 96.45 90 top
NOREF#249  -  []  24.74 113.16 90 top
NOREF#250  -  []  48.58 97.49 90 top
NOREF#251  -  []  120.06 31.02 0 top
NOREF#252  -  []  96.89 5.06 90 top
NOREF#253  -  []  26.29 105.36 0 top
NOREF#254  -  []  86.79 112.63 0 top
NOREF#255  -  []  81.01 107.34 0 top
NOREF#256  -  []  127.45 36.9 0 top
NOREF#257  -  []  111.85 106.4 0 top
NOREF#258  -  []  27.71 10.1 0 top
NOREF#259  -  []  35.38 46.68 0 top
NOREF#260  -  []  30.29 94.95 0 top
NOREF#261  -  []  100.7 62.68 90 top
NOREF#262  -  [unnamed#3]  87.08 62.9 90 top
NOREF#263  -  []  102.34 111.18 90 top
NOREF#264  -  []  24.74 113.16 90 top
NOREF#265  -  []  36.66 73.02 0 top
NOREF#266  -  []  75.31 107.34 0 top
NOREF#267  -  []  60.76 78.06 0 top
NOREF#268  -  []  33.38 47.05 90 top
NOREF#269  -  []  103.82 59.5 90 top
NOREF#270  -  []  114.29 1.95 0 top
NOREF#271  -  []  126.47 21.8 0 top
NOREF#272  -  []  117.94 6.47 0 top
NOREF#273  -  []  39.81 124.03 0 top
NOREF#274  -  []  14.64 37.16 0 top
NOREF#275  -  []  80.21 109.97 0 top
NOREF#276  -  []  61.11 83.79 0 top
NOREF#277  -  []  106.45 102.57 0 top
NOREF#278  -  []  24.74 113.16 0 top
NOREF#279  -  []  87.5 -33.27 0 top
NOREF#280  -  []  41.64 76.6 0 top
NOREF#281  -  []  50.66 116 0 top
NOREF#282  -  []  101.82 77.44 0 top
NOREF#283  -  []  107.95 104.07 0 top
NOREF#284  -  []  117.98 7.83 90 top
NOREF#285  -  []  45.97 72.37 0 top
NOREF#286  -  []  78.61 71.8 0 top
NOREF#287  -  []  82.06 109.78 0 top
NOREF#288  -  []  120.25 78.2 90 top
NOREF#289  -  []  53.58 94.95 0 top
NOREF#290  -  []  18.79 107.32 90 top
NOREF#291  -  []  44.89 71.95 0 top
NOREF#292  -  [unnamed#2]  12.09 82.19 180 top
NOREF#293  -  []  15.64 34.88 0 top
NOREF#294  -  []  126.84 0 90 top
NOREF#295  -  []  81.01 107.34 90 top
NOREF#296  -  []  27.45 22.27 0 top
NOREF#297  -  []  22.89 117.73 0 top
NOREF#298  -  []  96.04 6.11 90 top
NOREF#299  -  []  99.71 106.55 0 top
NOREF#300  -  []  16.63 92.69 0 top
NOREF#301  -  []  83.64 77.01 90 top
NOREF#302  -  []  31.29 107.9 0 top
NOREF#303  -  []  15.64 34.88 90 top
NOREF#304  -  []  126.16 0 90 top
NOREF#305  -  []  126.22 88.03 0 top
NOREF#306  -  []  123.19 0 0 top
NOREF#307  -  []  17.4 108.67 90 top
NOREF#308  -  []  86.68 109.83 0 top
NOREF#309  -  []  17.44 98.51 90 top
NOREF#310  -  []  24.07 66.84 90 top
NOREF#311  -  []  32.88 47.05 0 top
NOREF#312  -  []  83.26 109.78 90 top
NOREF#313  -  []  16.61 98.26 90 top
NOREF#314  -  []  17.65 92.09 0 top
NOREF#315  -  []  129.37 45.48 0 top
NOREF#316  -  [unnamed#2]  133.09 82.19 0 top
NOREF#317  -  []  100.95 107.27 0 top
NOREF#318  -  []  14.29 41.66 0 top
NOREF#319  -  []  48.63 116 0 top
NOREF#320  -  []  37.97 73.67 0 top
NOREF#321  -  []  119.07 18.96 90 top
NOREF#322  -  []  130.54 42.59 90 top
NOREF#323  -  []  14.41 88.1 90 top
NOREF#324  -  []  115.52 5.27 0 top
NOREF#325  -  []  77.31 5.06 0 top
NOREF#326  -  []  44.24 71.95 0 top
NOREF#327  -  []  89.54 88.16 0 top
NOREF#328  -  []  122.96 5.27 0 top
NOREF#329  -  []  131.44 50.69 0 top
NOREF#330  -  []  47.64 58.6 90 top
NOREF#331  -  []  81.01 107.34 90 top
NOREF#332  -  []  115.02 85.08 90 top
NOREF#333  -  []  128.19 77.98 0 top
NOREF#334  -  []  37.32 72.05 0 top
NOREF#335  -  []  15.38 47.05 0 top
NOREF#336  -  []  25.29 107.9 0 top
NOREF#337  -  []  39.68 101.37 90 top
NOREF#338  -  []  47.09 71.15 0 top
NOREF#339  -  []  48.58 107.9 90 top
NOREF#340  -  []  86.92 91.85 0 top
NOREF#341  -  []  48.03 113.16 90 top
NOREF#342  -  []  18.83 97.16 90 top
NOREF#343  -  []  16.61 97.76 0 top
NOREF#344  -  []  48.63 116 0 top
NOREF#345  -  []  37.97 78.87 0 top
NOREF#346  -  []  120.3 10.27 0 top
NOREF#347  -  []  81.46 110.8 0 top
NOREF#348  -  []  131.83 31.95 0 top
NOREF#349  -  []  126.43 75.58 90 top
NOREF#350  -  []  54.58 107.9 0 top
NOREF#351  -  []  113.65 0 0 top
NOREF#352  -  []  34.73 53.83 90 top
NOREF#353  -  []  90.82 91.85 0 top
NOREF#354  -  [unnamed#2]  133.07 32.4 0 top
NOREF#355  -  []  25.29 107.9 90 top
NOREF#356  -  []  111.59 93.07 0 top
NOREF#357  -  []  45.32 73.35 0 top
NOREF#358  -  []  104.89 92.77 0 top
NOREF#359  -  []  48.03 113.16 0 top
NOREF#360  -  []  37.32 78.55 0 top
NOREF#361  -  []  36.01 74.65 0 top
NOREF#362  -  []  127.49 80.21 90 top
NOREF#363  -  []  73.08 17.31 90 top
NOREF#364  -  [unnamed#2]  12.09 84.22 180 top
NOREF#365  -  [unnamed#2]  133.07 33.42 0 top
NOREF#366  -  []  104.49 91.57 90 top
NOREF#367  -  []  80.84 77.01 0 top
NOREF#368  -  []  127.67 21.8 90 top
NOREF#369  -  []  37.31 79.85 0 top
NOREF#370  -  []  117.86 96.45 0 top
NOREF#371  -  []  58.3 79.27 180 bottom
NOREF#372  -  []  107.43 6.24 180 bottom
NOREF#373  -  [unnamed#2]  30.12 4.87 180 bottom
NOREF#374  -  []  134.29 74.74 270 bottom
NOREF#375  -  []  62.96 65.7 180 bottom
NOREF#376  -  [unnamed#2]  126.06 83.26 180 bottom
NOREF#377  -  [unnamed#2]  99.92 3.4 180 bottom
P1  -  [CON_RJ45_2X1_TH_RA]  60.58 107.9 180 top
P2  -  [CON_RJ45_2X1_TH_RA]  37.29 107.9 180 top
Q3  -  [SOT23-40X40]  86.66 59.37 90 top
Q4  -  [SOT323_3]  94.09 50.56 0 top
R5  1.0K  [RC0402_25]  117.23 80.94 180 bottom
R6  0  [RC0402_25]  117.25 81.82 180 bottom
R7  -  [RC0402_25]  117.26 81.83 0 top
R10  1.0K  [RC0402_25]  117.23 80.97 180 top
R11  -  [RC0402_25]  115.05 87.14 270 top
R13  -  [RC0402_25]  121.38 48.15 0 bottom
R15  0  [RC0402_25]  125.84 47.64 0 bottom
R25  0  [RC0402_25]  21.85 72.53 270 top
R33  -  [RC0402_25]  89.33 57.65 270 bottom
R36  -  [RC0402_25]  88.23 59.23 180 bottom
R52  -  [RC0402_25]  108.95 34.94 0 top
R55  -  [RC0402_25]  125.84 46.5 180 top
R56  -  [RC0402_25]  125.84 49.67 180 top
R59  -  [RC0402_25]  125.79 44.52 0 top
R60  -  [RC0402_25]  127.87 43.07 180 top
R62  0  [RC0402_25]  125.84 43.65 0 top
R64  -  [RC0402_25]  127.87 41.93 0 top
R66  -  [RC0402_25]  128.51 53.99 270 bottom
R67  -  [RC0402_25]  125.84 47.64 0 top
R82  -  [RC0402_25]  70.18 15.86 90 bottom
R83  -  [RC0402_25]  71.26 19.12 180 bottom
R84  -  [RC0402_25]  71.32 17.6 180 bottom
R91  -  [RC0402_25]  79.59 47.96 180 bottom
R92  -  [RC0402_25]  49.01 51.25 90 top
R93  -  [RC0402_25]  79.44 45.81 180 bottom
R94  -  [RC0402_25]  48.75 54.12 270 top
R95  -  [RC0402_25]  79.53 52.95 180 bottom
R96  -  [RC0402_25]  45.58 47.13 270 top
R97  -  [RC0402_25]  88.71 37.36 180 bottom
R98  -  [RC0402_25]  45.58 44.47 90 top
R100  -  [RC0402_25]  91.17 37.74 90 bottom
R101  -  [RC0402_25]  85.96 59.92 0 bottom
R102  -  [RC0402_25]  45.83 37.74 90 bottom
R103  -  [RC0402_25]  97.95 15 90 top
R104  240  [RC0402_25]  86.72 14.66 90 top
R105  -  [RC0402_25]  64.02 14.66 90 top
R106  240  [RC0402_25]  52.31 14.62 90 top
R107  -  [RC0402_25]  75.35 14.62 90 top
R111  -  [RC0402_25]  38.65 9.36 180 top
R112  -  [RC0402_25]  38.62 6.56 180 top
R113  -  [RC0402_25]  49.26 3.57 270 bottom
R114  -  [RC0402_25]  38.61 11.62 180 top
R115  -  [RC0402_25]  48.37 3.57 270 top
R116  -  [RC0402_25]  38.63 10.43 180 top
R117  -  [RC0402_25]  49.26 3.57 270 top
R118  -  [RC0402_25]  38.63 8.42 180 top
R119  -  [RC0402_25]  51.04 3.57 270 top
R120  -  [RC0402_25]  38.61 11.62 180 bottom
R121  -  [RC0402_25]  50.15 3.57 270 bottom
R122  -  [RC0402_25]  47.48 3.57 270 top
R123  -  [RC0402_25]  38.64 7.48 180 top
R124  -  [RC0402_25]  50.15 3.57 270 top
R125  -  [RC0402_25]  47.48 3.57 270 bottom
R126  -  [RC0402_25]  38.62 15.01 180 top
R127  -  [RC0402_25]  44.54 3.57 270 top
R128  -  [RC0402_25]  48.37 3.57 270 bottom
R129  -  [RC0402_25]  38.64 12.5 180 top
R130  -  [RC0402_25]  38.61 14.18 180 top
R131  -  [RC0402_25]  38.6 16.76 180 top
R132  -  [RC0402_25]  52.92 3.62 270 top
R133  -  [RC0402_25]  38.62 15.88 180 top
R134  -  [RC0402_25]  38.64 5.57 180 top
R135  -  [RC0402_25]  39.16 17.72 180 top
R136  -  [RC0402_25]  46.59 3.57 270 top
R137  -  [RC0402_25]  46.24 4.23 270 bottom
R138  -  [RC0402_25]  45.4 4.21 270 bottom
R140  -  [RC0402_25]  62.82 31.46 90 top
R141  -  [RC0402_25]  64.93 31.49 90 top
R142  -  [RC0201]  52.06 4.18 90 top
R143  -  [RC0402_25]  92.62 60.64 180 bottom
R144  4.7K  [RC0402_25]  91.54 56.84 0 top
R157  -  [RC0402_25]  108.93 58.49 270 bottom
R158  -  [RC0402_25]  83.43 39.72 0 bottom
R160  -  [RC0402_25]  83.43 44.92 180 bottom
R161  -  [RC0402_25]  88.86 45.3 90 bottom
R167  -  [RC0402_25]  84.78 51.69 270 bottom
R168  -  [RC0402_25]  86.21 45.3 90 bottom
R169  -  [RC0402_25]  79.53 54.88 180 bottom
R170  -  [RC0402_25]  87.23 45.3 90 bottom
R171  -  [RC0402_25]  87.23 45.3 90 top
R172  4.7K  [RC0402_25]  83.43 45.81 180 top
R177  4.7K  [RC0402_25]  86.21 45.3 270 top
R185  -  [RC0402_25]  83.43 44.92 0 top
R186  -  [RC0402_25]  23.79 78.75 0 top
R187  -  [RC0402_25]  85.96 43.49 0 bottom
R188  0  [RC0402_25]  21.02 85.97 0 bottom
R191  -  [RC0402_25]  94.63 47.19 90 top
R192  -  [RC0402_25]  93.16 47.49 270 top
R202  -  [RC1206_OV]  43.29 115.59 270 top
R203  -  [RC0402_25]  83.43 40.74 180 bottom
R204  -  [RC0402_25]  83.43 42.76 180 bottom
R205  -  [RC0402_25]  83.43 43.78 180 bottom
R228  -  [RC0402_25]  85.91 47.59 0 bottom
R239  -  [RC0402_25]  65.26 56.2 90 bottom
R241  -  [RC0402_25]  67.07 58.31 90 bottom
R242  -  [RC0402_25]  111.95 89.6 270 bottom
R243  -  [RC0402_25]  109.89 92.35 90 top
R244  -  [RC0402_25]  112.74 99.33 0 top
R245  -  [RC0402_25]  101.53 86.35 90 bottom
R248  -  [RC0402_25]  74.65 64.43 90 bottom
R249  -  [RC0402_25]  71.96 64.38 90 bottom
R255  0  [RC0402_25]  79.53 54.88 180 top
R257  -  [RC0402_25]  72.92 64.38 90 bottom
R258  -  [RC0402_25]  46.85 53.74 0 top
R259  -  [RC0402_25]  44.56 47.13 270 top
R260  -  [RC0201]  60.09 50.01 0 bottom
R261  -  [RC0201]  61.13 45.43 180 bottom
R277  -  [RC0402_25]  21.48 69.66 0 top
R298  -  [RC0402_25]  121.52 16.73 180 top
R299  -  [RC0402_25]  123.32 16.72 180 bottom
R301  -  [RC0402_25]  120.64 20.36 270 top
R302  -  [RC0402_25]  116.62 19.19 0 top
R303  -  [RC0402_25]  118.25 22.34 0 bottom
R304  -  [RC0402_25]  123.86 22.01 180 bottom
R305  -  [RC0402_25]  117.59 26.71 0 top
R355  -  [RC0402_25]  15.28 81.07 90 top
R401  0  [RC0402_25]  72.77 115.28 180 top
R409  -  [RC0402_25]  90.17 65.67 90 top
R412  -  [RC0402_25]  93.41 65.5 180 bottom
R471  0  [RC0402_25]  79.53 53.99 0 top
R473  -  [RC0402_25]  82.1 56.57 0 bottom
R474  -  [RC0402_25]  73.81 64.38 90 bottom
R558  -  [RC0402_25]  104.76 16.02 0 bottom
R560  -  [RC0402_25]  77.56 56.99 90 top
R643  220  [RC0402_25]  63.41 87.9 180 top
R644  220  [RC0402_25]  46.98 87.77 0 top
R645  220  [RC0402_25]  64.5 114.57 180 top
R646  220  [RC0402_25]  44.31 109.87 0 top
R647  -  [RC0402_25]  41.39 109.87 180 top
R648  -  [RC0402_25]  21.07 114.65 0 top
R649  -  [RC0402_25]  35.55 88.16 180 top
R650  -  [RC0402_25]  22.85 87.9 0 top
R651  4.7K  [RC0402_25]  33.35 73.25 0 bottom
R652  -  [RC0402_25]  33.35 72.23 0 top
R653  -  [RC0402_25]  33.35 73.25 0 top
R654  -  [RC0402_25]  33.35 76.04 180 top
R655  -  [RC0402_25]  33.35 74.26 180 top
R656  -  [RC0402_25]  33.35 71.21 180 bottom
R657  -  [RC0402_25]  48.85 75.89 0 top
R658  -  [RC0402_25]  48.85 76.75 0 top
R659  -  [RC0402_25]  48.85 77.61 0 top
R660  0  [RC0402_25]  33.35 71.21 180 top
R661  -  [RC0402_25]  33.35 75.15 180 top
R662  -  [RC0402_25]  41.64 86.76 90 top
R663  -  [RC0402_25]  46.14 69.32 0 top
R666  4.7K  [RC0402_25]  20.87 47.07 90 top
R667  4.7K  [RC0402_25]  20.01 51.21 90 top
R668  4.7K  [RC0402_25]  20.9 51.21 90 top
R669  4.7K  [RC0402_25]  19.88 47.07 270 top
